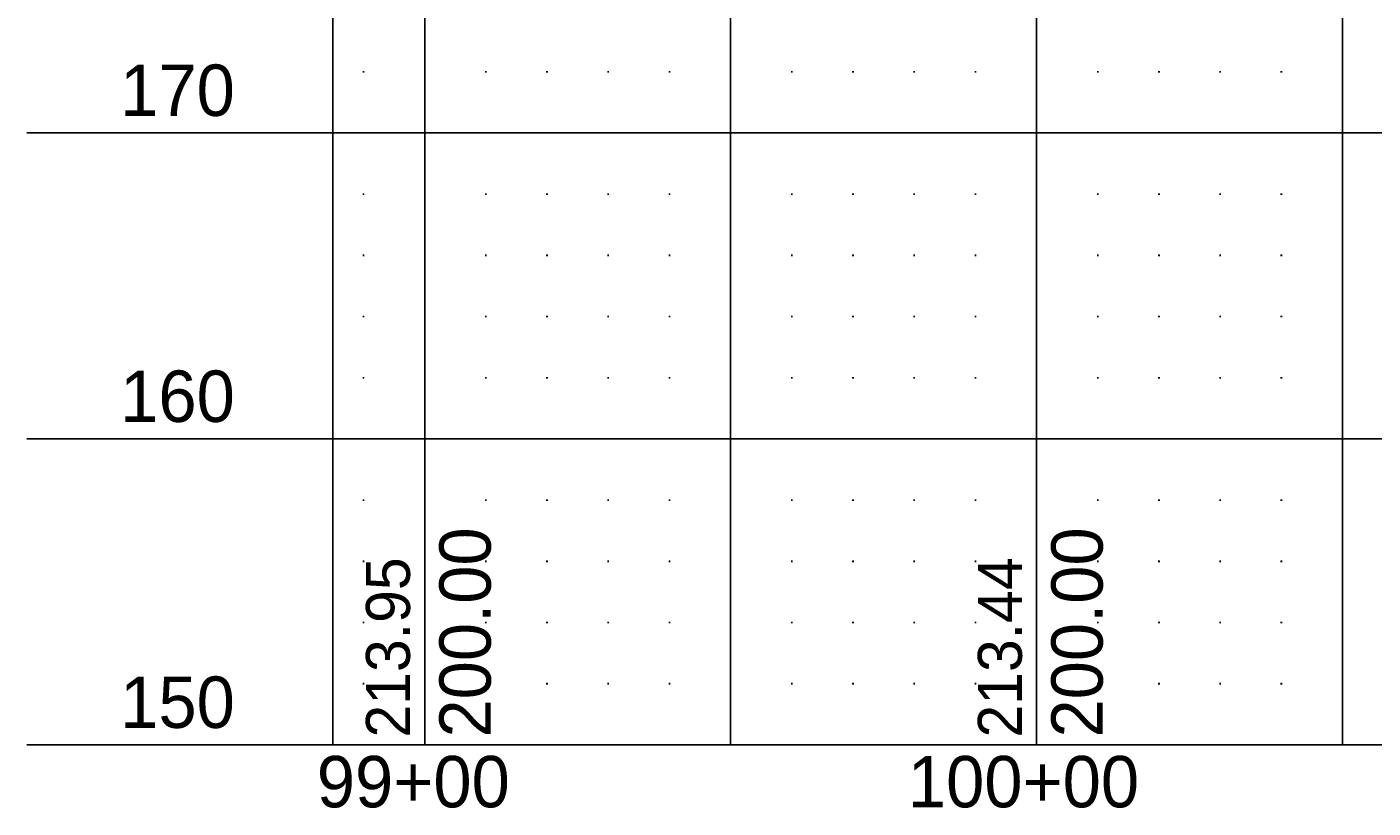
# Model space of a CAD drawing. Extents: x 471 to 2121, y 140 to 650.
# Drawn here: x 471.1 to 691, y 139.7 to 267.3 of the extents above; entities that cross this region are included whole.
import ezdxf

# ---------------------------------------------------------------- set-up
doc = ezdxf.new("R2010")
doc.units = 0
for name, color, linetype in [('DSN_DRFT_Border Grid', 7, 'Continuous'), ('DSN_RDWY_Prof Annotation', 7, 'Continuous'), ('EX_Profile Annotation', 7, 'Continuous')]:
    doc.layers.add(name, color=color, linetype=linetype)

msp = doc.modelspace()

# ---------------------------------------------------------------- linework, layer by layer
at = {"layer": 'DSN_DRFT_Border Grid'}
for p, q in [((521.06, 150), (521.06, 650)), ((521.06, 150), (521.06, 650)), ((536.06, 150), (536.06, 650)), ((536.06, 150), (536.06, 650)), ((586.06, 150), (586.06, 650)), ((586.06, 150), (586.06, 650)), ((636.06, 150), (636.06, 650)), ((636.06, 150), (636.06, 650)), ((686.06, 150), (686.06, 650)), ((686.06, 150), (686.06, 650)), ((526.18, 260), (525.94, 260)), ((526.18, 260), (525.94, 260)), ((526.06, 260.12), (526.06, 259.88)), ((526.06, 260.12), (526.06, 259.88)), ((546.18, 260), (545.94, 260)), ((546.18, 260), (545.94, 260)), ((546.06, 260.12), (546.06, 259.88)), ((546.06, 260.12), (546.06, 259.88)), ((556.18, 260), (555.94, 260)), ((556.18, 260), (555.94, 260)), ((556.06, 260.12), (556.06, 259.88)), ((556.06, 260.12), (556.06, 259.88)), ((566.18, 260), (565.94, 260)), ((566.18, 260), (565.94, 260)), ((566.06, 260.12), (566.06, 259.88)), ((566.06, 260.12), (566.06, 259.88)), ((576.18, 260), (575.94, 260)), ((576.18, 260), (575.94, 260)), ((576.06, 260.12), (576.06, 259.88)), ((576.06, 260.12), (576.06, 259.88)), ((596.18, 260), (595.94, 260)), ((596.18, 260), (595.94, 260)), ((596.06, 260.12), (596.06, 259.88)), ((596.06, 260.12), (596.06, 259.88)), ((606.18, 260), (605.94, 260)), ((606.18, 260), (605.94, 260)), ((606.06, 260.12), (606.06, 259.88)), ((606.06, 260.12), (606.06, 259.88)), ((616.18, 260), (615.94, 260)), ((616.18, 260), (615.94, 260)), ((616.06, 260.12), (616.06, 259.88)), ((616.06, 260.12), (616.06, 259.88)), ((626.18, 260), (625.94, 260)), ((626.18, 260), (625.94, 260)), ((626.06, 260.12), (626.06, 259.88)), ((626.06, 260.12), (626.06, 259.88)), ((646.18, 260), (645.94, 260)), ((646.18, 260), (645.94, 260)), ((646.06, 260.12), (646.06, 259.88)), ((646.06, 260.12), (646.06, 259.88)), ((656.18, 260), (655.94, 260)), ((656.18, 260), (655.94, 260)), ((656.06, 260.12), (656.06, 259.88)), ((656.06, 260.12), (656.06, 259.88)), ((666.18, 260), (665.94, 260)), ((666.18, 260), (665.94, 260)), ((666.06, 260.12), (666.06, 259.88)), ((666.06, 260.12), (666.06, 259.88)), ((676.18, 260), (675.94, 260)), ((676.18, 260), (675.94, 260)), ((676.06, 260.12), (676.06, 259.88)), ((676.06, 260.12), (676.06, 259.88)), ((471.06, 250), (521.06, 250)), ((521.06, 250), (2071.06, 250)), ((521.06, 250), (2071.06, 250)), ((526.18, 240), (525.94, 240)), ((526.18, 240), (525.94, 240)), ((526.06, 240.12), (526.06, 239.88)), ((526.06, 240.12), (526.06, 239.88)), ((546.18, 240), (545.94, 240)), ((546.18, 240), (545.94, 240)), ((546.06, 240.12), (546.06, 239.88)), ((546.06, 240.12), (546.06, 239.88)), ((556.18, 240), (555.94, 240)), ((556.18, 240), (555.94, 240)), ((556.06, 240.12), (556.06, 239.88)), ((556.06, 240.12), (556.06, 239.88)), ((566.18, 240), (565.94, 240)), ((566.18, 240), (565.94, 240)), ((566.06, 240.12), (566.06, 239.88)), ((566.06, 240.12), (566.06, 239.88)), ((576.18, 240), (575.94, 240)), ((576.18, 240), (575.94, 240)), ((576.06, 240.12), (576.06, 239.88)), ((576.06, 240.12), (576.06, 239.88)), ((596.18, 240), (595.94, 240)), ((596.18, 240), (595.94, 240)), ((596.06, 240.12), (596.06, 239.88)), ((596.06, 240.12), (596.06, 239.88)), ((606.18, 240), (605.94, 240)), ((606.18, 240), (605.94, 240)), ((606.06, 240.12), (606.06, 239.88)), ((606.06, 240.12), (606.06, 239.88)), ((616.18, 240), (615.94, 240)), ((616.18, 240), (615.94, 240)), ((616.06, 240.12), (616.06, 239.88)), ((616.06, 240.12), (616.06, 239.88)), ((626.18, 240), (625.94, 240)), ((626.18, 240), (625.94, 240)), ((626.06, 240.12), (626.06, 239.88)), ((626.06, 240.12), (626.06, 239.88)), ((646.18, 240), (645.94, 240)), ((646.18, 240), (645.94, 240)), ((646.06, 240.12), (646.06, 239.88)), ((646.06, 240.12), (646.06, 239.88)), ((656.18, 240), (655.94, 240)), ((656.18, 240), (655.94, 240)), ((656.06, 240.12), (656.06, 239.88)), ((656.06, 240.12), (656.06, 239.88)), ((666.18, 240), (665.94, 240)), ((666.18, 240), (665.94, 240)), ((666.06, 240.12), (666.06, 239.88)), ((666.06, 240.12), (666.06, 239.88)), ((676.18, 240), (675.94, 240)), ((676.18, 240), (675.94, 240)), ((676.06, 240.12), (676.06, 239.88)), ((676.06, 240.12), (676.06, 239.88)), ((526.18, 230), (525.94, 230)), ((526.18, 230), (525.94, 230)), ((526.06, 230.12), (526.06, 229.88)), ((526.06, 230.12), (526.06, 229.88)), ((546.18, 230), (545.94, 230)), ((546.18, 230), (545.94, 230)), ((546.06, 230.12), (546.06, 229.88)), ((546.06, 230.12), (546.06, 229.88)), ((556.18, 230), (555.94, 230)), ((556.18, 230), (555.94, 230)), ((556.06, 230.12), (556.06, 229.88)), ((556.06, 230.12), (556.06, 229.88)), ((566.18, 230), (565.94, 230)), ((566.18, 230), (565.94, 230)), ((566.06, 230.12), (566.06, 229.88)), ((566.06, 230.12), (566.06, 229.88)), ((576.18, 230), (575.94, 230)), ((576.18, 230), (575.94, 230)), ((576.06, 230.12), (576.06, 229.88)), ((576.06, 230.12), (576.06, 229.88)), ((596.18, 230), (595.94, 230)), ((596.18, 230), (595.94, 230)), ((596.06, 230.12), (596.06, 229.88)), ((596.06, 230.12), (596.06, 229.88)), ((606.18, 230), (605.94, 230)), ((606.18, 230), (605.94, 230)), ((606.06, 230.12), (606.06, 229.88)), ((606.06, 230.12), (606.06, 229.88)), ((616.18, 230), (615.94, 230)), ((616.18, 230), (615.94, 230)), ((616.06, 230.12), (616.06, 229.88)), ((616.06, 230.12), (616.06, 229.88)), ((626.18, 230), (625.94, 230)), ((626.18, 230), (625.94, 230)), ((626.06, 230.12), (626.06, 229.88)), ((626.06, 230.12), (626.06, 229.88)), ((646.18, 230), (645.94, 230)), ((646.18, 230), (645.94, 230)), ((646.06, 230.12), (646.06, 229.88)), ((646.06, 230.12), (646.06, 229.88)), ((656.18, 230), (655.94, 230)), ((656.18, 230), (655.94, 230)), ((656.06, 230.12), (656.06, 229.88)), ((656.06, 230.12), (656.06, 229.88)), ((666.18, 230), (665.94, 230)), ((666.18, 230), (665.94, 230)), ((666.06, 230.12), (666.06, 229.88)), ((666.06, 230.12), (666.06, 229.88)), ((676.18, 230), (675.94, 230)), ((676.18, 230), (675.94, 230)), ((676.06, 230.12), (676.06, 229.88)), ((676.06, 230.12), (676.06, 229.88)), ((526.18, 220), (525.94, 220)), ((526.18, 220), (525.94, 220)), ((526.06, 220.12), (526.06, 219.88)), ((526.06, 220.12), (526.06, 219.88)), ((546.18, 220), (545.94, 220)), ((546.18, 220), (545.94, 220)), ((546.06, 220.12), (546.06, 219.88)), ((546.06, 220.12), (546.06, 219.88)), ((556.18, 220), (555.94, 220)), ((556.18, 220), (555.94, 220)), ((556.06, 220.12), (556.06, 219.88)), ((556.06, 220.12), (556.06, 219.88)), ((566.18, 220), (565.94, 220)), ((566.18, 220), (565.94, 220)), ((566.06, 220.12), (566.06, 219.88)), ((566.06, 220.12), (566.06, 219.88)), ((576.18, 220), (575.94, 220)), ((576.18, 220), (575.94, 220)), ((576.06, 220.12), (576.06, 219.88)), ((576.06, 220.12), (576.06, 219.88)), ((596.18, 220), (595.94, 220)), ((596.18, 220), (595.94, 220)), ((596.06, 220.12), (596.06, 219.88)), ((596.06, 220.12), (596.06, 219.88)), ((606.18, 220), (605.94, 220)), ((606.18, 220), (605.94, 220)), ((606.06, 220.12), (606.06, 219.88)), ((606.06, 220.12), (606.06, 219.88)), ((616.18, 220), (615.94, 220)), ((616.18, 220), (615.94, 220)), ((616.06, 220.12), (616.06, 219.88)), ((616.06, 220.12), (616.06, 219.88)), ((626.18, 220), (625.94, 220)), ((626.18, 220), (625.94, 220)), ((626.06, 220.12), (626.06, 219.88)), ((626.06, 220.12), (626.06, 219.88)), ((646.18, 220), (645.94, 220)), ((646.18, 220), (645.94, 220)), ((646.06, 220.12), (646.06, 219.88)), ((646.06, 220.12), (646.06, 219.88)), ((656.18, 220), (655.94, 220)), ((656.18, 220), (655.94, 220)), ((656.06, 220.12), (656.06, 219.88)), ((656.06, 220.12), (656.06, 219.88)), ((666.18, 220), (665.94, 220)), ((666.18, 220), (665.94, 220)), ((666.06, 220.12), (666.06, 219.88)), ((666.06, 220.12), (666.06, 219.88)), ((676.18, 220), (675.94, 220)), ((676.18, 220), (675.94, 220)), ((676.06, 220.12), (676.06, 219.88)), ((676.06, 220.12), (676.06, 219.88)), ((526.18, 210), (525.94, 210)), ((526.18, 210), (525.94, 210)), ((526.06, 210.12), (526.06, 209.88)), ((526.06, 210.12), (526.06, 209.88)), ((546.18, 210), (545.94, 210)), ((546.18, 210), (545.94, 210)), ((546.06, 210.12), (546.06, 209.88)), ((546.06, 210.12), (546.06, 209.88)), ((556.18, 210), (555.94, 210)), ((556.18, 210), (555.94, 210)), ((556.06, 210.12), (556.06, 209.88)), ((556.06, 210.12), (556.06, 209.88)), ((566.18, 210), (565.94, 210)), ((566.18, 210), (565.94, 210)), ((566.06, 210.12), (566.06, 209.88)), ((566.06, 210.12), (566.06, 209.88)), ((576.18, 210), (575.94, 210)), ((576.18, 210), (575.94, 210)), ((576.06, 210.12), (576.06, 209.88)), ((576.06, 210.12), (576.06, 209.88)), ((596.18, 210), (595.94, 210)), ((596.18, 210), (595.94, 210)), ((596.06, 210.12), (596.06, 209.88)), ((596.06, 210.12), (596.06, 209.88)), ((606.18, 210), (605.94, 210)), ((606.18, 210), (605.94, 210)), ((606.06, 210.12), (606.06, 209.88)), ((606.06, 210.12), (606.06, 209.88)), ((616.18, 210), (615.94, 210)), ((616.18, 210), (615.94, 210)), ((616.06, 210.12), (616.06, 209.88)), ((616.06, 210.12), (616.06, 209.88)), ((626.18, 210), (625.94, 210)), ((626.18, 210), (625.94, 210)), ((626.06, 210.12), (626.06, 209.88)), ((626.06, 210.12), (626.06, 209.88)), ((646.18, 210), (645.94, 210)), ((646.18, 210), (645.94, 210)), ((646.06, 210.12), (646.06, 209.88)), ((646.06, 210.12), (646.06, 209.88)), ((656.18, 210), (655.94, 210)), ((656.18, 210), (655.94, 210)), ((656.06, 210.12), (656.06, 209.88)), ((656.06, 210.12), (656.06, 209.88)), ((666.18, 210), (665.94, 210)), ((666.18, 210), (665.94, 210)), ((666.06, 210.12), (666.06, 209.88)), ((666.06, 210.12), (666.06, 209.88)), ((676.18, 210), (675.94, 210)), ((676.18, 210), (675.94, 210)), ((676.06, 210.12), (676.06, 209.88)), ((676.06, 210.12), (676.06, 209.88)), ((471.06, 200), (521.06, 200)), ((521.06, 200), (2071.06, 200)), ((521.06, 200), (2071.06, 200)), ((526.18, 190), (525.94, 190)), ((526.18, 190), (525.94, 190)), ((526.06, 190.12), (526.06, 189.88)), ((526.06, 190.12), (526.06, 189.88)), ((546.18, 190), (545.94, 190)), ((546.18, 190), (545.94, 190)), ((546.06, 190.12), (546.06, 189.88)), ((546.06, 190.12), (546.06, 189.88)), ((556.18, 190), (555.94, 190)), ((556.18, 190), (555.94, 190)), ((556.06, 190.12), (556.06, 189.88)), ((556.06, 190.12), (556.06, 189.88)), ((566.18, 190), (565.94, 190)), ((566.18, 190), (565.94, 190)), ((566.06, 190.12), (566.06, 189.88)), ((566.06, 190.12), (566.06, 189.88)), ((576.18, 190), (575.94, 190)), ((576.18, 190), (575.94, 190)), ((576.06, 190.12), (576.06, 189.88)), ((576.06, 190.12), (576.06, 189.88)), ((596.18, 190), (595.94, 190)), ((596.18, 190), (595.94, 190)), ((596.06, 190.12), (596.06, 189.88)), ((596.06, 190.12), (596.06, 189.88)), ((606.18, 190), (605.94, 190)), ((606.18, 190), (605.94, 190)), ((606.06, 190.12), (606.06, 189.88)), ((606.06, 190.12), (606.06, 189.88)), ((616.18, 190), (615.94, 190)), ((616.18, 190), (615.94, 190)), ((616.06, 190.12), (616.06, 189.88)), ((616.06, 190.12), (616.06, 189.88)), ((626.18, 190), (625.94, 190)), ((626.18, 190), (625.94, 190)), ((626.06, 190.12), (626.06, 189.88)), ((626.06, 190.12), (626.06, 189.88)), ((646.18, 190), (645.94, 190)), ((646.18, 190), (645.94, 190)), ((646.06, 190.12), (646.06, 189.88)), ((646.06, 190.12), (646.06, 189.88)), ((656.18, 190), (655.94, 190)), ((656.18, 190), (655.94, 190)), ((656.06, 190.12), (656.06, 189.88)), ((656.06, 190.12), (656.06, 189.88)), ((666.18, 190), (665.94, 190)), ((666.18, 190), (665.94, 190)), ((666.06, 190.12), (666.06, 189.88)), ((666.06, 190.12), (666.06, 189.88)), ((676.18, 190), (675.94, 190)), ((676.18, 190), (675.94, 190)), ((676.06, 190.12), (676.06, 189.88)), ((676.06, 190.12), (676.06, 189.88)), ((526.18, 180), (525.94, 180)), ((526.18, 180), (525.94, 180)), ((526.06, 180.12), (526.06, 179.88)), ((526.06, 180.12), (526.06, 179.88)), ((546.18, 180), (545.94, 180)), ((546.18, 180), (545.94, 180)), ((546.06, 180.12), (546.06, 179.88)), ((546.06, 180.12), (546.06, 179.88)), ((556.18, 180), (555.94, 180)), ((556.18, 180), (555.94, 180)), ((556.06, 180.12), (556.06, 179.88)), ((556.06, 180.12), (556.06, 179.88)), ((566.18, 180), (565.94, 180)), ((566.18, 180), (565.94, 180)), ((566.06, 180.12), (566.06, 179.88)), ((566.06, 180.12), (566.06, 179.88)), ((576.18, 180), (575.94, 180)), ((576.18, 180), (575.94, 180)), ((576.06, 180.12), (576.06, 179.88)), ((576.06, 180.12), (576.06, 179.88)), ((596.18, 180), (595.94, 180)), ((596.18, 180), (595.94, 180)), ((596.06, 180.12), (596.06, 179.88)), ((596.06, 180.12), (596.06, 179.88)), ((606.18, 180), (605.94, 180)), ((606.18, 180), (605.94, 180)), ((606.06, 180.12), (606.06, 179.88)), ((606.06, 180.12), (606.06, 179.88)), ((616.18, 180), (615.94, 180)), ((616.18, 180), (615.94, 180)), ((616.06, 180.12), (616.06, 179.88)), ((616.06, 180.12), (616.06, 179.88)), ((626.18, 180), (625.94, 180)), ((626.18, 180), (625.94, 180)), ((626.06, 180.12), (626.06, 179.88)), ((626.06, 180.12), (626.06, 179.88)), ((646.18, 180), (645.94, 180)), ((646.18, 180), (645.94, 180)), ((646.06, 180.12), (646.06, 179.88)), ((646.06, 180.12), (646.06, 179.88)), ((656.18, 180), (655.94, 180)), ((656.18, 180), (655.94, 180)), ((656.06, 180.12), (656.06, 179.88)), ((656.06, 180.12), (656.06, 179.88)), ((666.18, 180), (665.94, 180)), ((666.18, 180), (665.94, 180)), ((666.06, 180.12), (666.06, 179.88)), ((666.06, 180.12), (666.06, 179.88)), ((676.18, 180), (675.94, 180)), ((676.18, 180), (675.94, 180)), ((676.06, 180.12), (676.06, 179.88)), ((676.06, 180.12), (676.06, 179.88)), ((526.18, 170), (525.94, 170)), ((526.18, 170), (525.94, 170)), ((526.06, 170.12), (526.06, 169.88)), ((526.06, 170.12), (526.06, 169.88)), ((546.18, 170), (545.94, 170)), ((546.18, 170), (545.94, 170)), ((546.06, 170.12), (546.06, 169.88)), ((546.06, 170.12), (546.06, 169.88)), ((556.18, 170), (555.94, 170)), ((556.18, 170), (555.94, 170)), ((556.06, 170.12), (556.06, 169.88)), ((556.06, 170.12), (556.06, 169.88)), ((566.18, 170), (565.94, 170)), ((566.18, 170), (565.94, 170)), ((566.06, 170.12), (566.06, 169.88)), ((566.06, 170.12), (566.06, 169.88)), ((576.18, 170), (575.94, 170)), ((576.18, 170), (575.94, 170)), ((576.06, 170.12), (576.06, 169.88)), ((576.06, 170.12), (576.06, 169.88)), ((596.18, 170), (595.94, 170)), ((596.18, 170), (595.94, 170)), ((596.06, 170.12), (596.06, 169.88)), ((596.06, 170.12), (596.06, 169.88)), ((606.18, 170), (605.94, 170)), ((606.18, 170), (605.94, 170)), ((606.06, 170.12), (606.06, 169.88)), ((606.06, 170.12), (606.06, 169.88)), ((616.18, 170), (615.94, 170)), ((616.18, 170), (615.94, 170)), ((616.06, 170.12), (616.06, 169.88)), ((616.06, 170.12), (616.06, 169.88)), ((626.18, 170), (625.94, 170)), ((626.18, 170), (625.94, 170)), ((626.06, 170.12), (626.06, 169.88)), ((626.06, 170.12), (626.06, 169.88)), ((646.18, 170), (645.94, 170)), ((646.18, 170), (645.94, 170)), ((646.06, 170.12), (646.06, 169.88)), ((646.06, 170.12), (646.06, 169.88)), ((656.18, 170), (655.94, 170)), ((656.18, 170), (655.94, 170)), ((656.06, 170.12), (656.06, 169.88)), ((656.06, 170.12), (656.06, 169.88)), ((666.18, 170), (665.94, 170)), ((666.18, 170), (665.94, 170)), ((666.06, 170.12), (666.06, 169.88)), ((666.06, 170.12), (666.06, 169.88)), ((676.18, 170), (675.94, 170)), ((676.18, 170), (675.94, 170)), ((676.06, 170.12), (676.06, 169.88)), ((676.06, 170.12), (676.06, 169.88)), ((526.18, 160), (525.94, 160)), ((526.18, 160), (525.94, 160)), ((526.06, 160.12), (526.06, 159.88)), ((526.06, 160.12), (526.06, 159.88)), ((546.18, 160), (545.94, 160)), ((546.18, 160), (545.94, 160)), ((546.06, 160.12), (546.06, 159.88)), ((546.06, 160.12), (546.06, 159.88)), ((556.18, 160), (555.94, 160)), ((556.18, 160), (555.94, 160)), ((556.06, 160.12), (556.06, 159.88)), ((556.06, 160.12), (556.06, 159.88)), ((566.18, 160), (565.94, 160)), ((566.18, 160), (565.94, 160)), ((566.06, 160.12), (566.06, 159.88)), ((566.06, 160.12), (566.06, 159.88)), ((576.18, 160), (575.94, 160)), ((576.18, 160), (575.94, 160)), ((576.06, 160.12), (576.06, 159.88)), ((576.06, 160.12), (576.06, 159.88)), ((596.18, 160), (595.94, 160)), ((596.18, 160), (595.94, 160)), ((596.06, 160.12), (596.06, 159.88)), ((596.06, 160.12), (596.06, 159.88)), ((606.18, 160), (605.94, 160)), ((606.18, 160), (605.94, 160)), ((606.06, 160.12), (606.06, 159.88)), ((606.06, 160.12), (606.06, 159.88)), ((616.18, 160), (615.94, 160)), ((616.18, 160), (615.94, 160)), ((616.06, 160.12), (616.06, 159.88)), ((616.06, 160.12), (616.06, 159.88)), ((626.18, 160), (625.94, 160)), ((626.18, 160), (625.94, 160)), ((626.06, 160.12), (626.06, 159.88)), ((626.06, 160.12), (626.06, 159.88)), ((646.18, 160), (645.94, 160)), ((646.18, 160), (645.94, 160)), ((646.06, 160.12), (646.06, 159.88)), ((646.06, 160.12), (646.06, 159.88)), ((656.18, 160), (655.94, 160)), ((656.18, 160), (655.94, 160)), ((656.06, 160.12), (656.06, 159.88)), ((656.06, 160.12), (656.06, 159.88)), ((666.18, 160), (665.94, 160)), ((666.18, 160), (665.94, 160)), ((666.06, 160.12), (666.06, 159.88)), ((666.06, 160.12), (666.06, 159.88)), ((676.18, 160), (675.94, 160)), ((676.18, 160), (675.94, 160)), ((676.06, 160.12), (676.06, 159.88)), ((676.06, 160.12), (676.06, 159.88)), ((471.06, 150), (521.06, 150)), ((521.06, 150), (2071.06, 150)), ((521.06, 150), (2071.06, 150))]:
    msp.add_line(p, q, dxfattribs=at)

# ---------------------------------------------------------------- texts
at = {"layer": 'DSN_RDWY_Prof Annotation'}
for s, p in [('170', (486.3, 252.78)), ('170', (486.3, 252.78)), ('160', (486.3, 202.78)), ('160', (486.3, 202.78)), ('150', (486.3, 152.78)), ('150', (486.3, 152.78)), ('99+00', (518.43, 139.8)), ('99+00', (518.43, 139.8)), ('100+00', (615.02, 139.8)), ('100+00', (615.02, 139.8))]:
    msp.add_text(s, height=8.4, dxfattribs=at).set_placement(p)
for p in [(546.86, 151.2), (646.86, 151.2)]:
    msp.add_text('200.00', height=8.4, rotation=90, dxfattribs=at).set_placement(p)
at = {"layer": 'EX_Profile Annotation'}
for s, p in [('213.95', (533.66, 151.2)), ('213.44', (633.66, 151.2))]:
    msp.add_text(s, height=7.2, rotation=90, dxfattribs=at).set_placement(p)

doc.saveas('drawing.dxf')
